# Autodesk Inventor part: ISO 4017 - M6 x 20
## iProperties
Created: 2006-11
Part Number: ISO 4017 - M6 x 20
Material: Stahl, weich, unlegiert
Description: Sechskantschraube
Vendor: Autodesk Inc.
Document SubType Name: Modeling
Standard: ISO 4017
Designer: Schmidt
Standards Organization: DIN
Language: de-DE
Size Designation: M6 x 20
Categories: <MemberInstance Version="R10.0.0"><Categories><Category DisplayName="Schrauben" InternalName="e4da775c-781d-43d5-af7c-5136215cf5a6" Mnemonic="FSTN"><Category Di
Density: 7.86 g/cm^3
Author: Schmidt
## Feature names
1. Körper [Revolution]
2. Kopf [Extrusion]
3. Fase1 [Revolution]
4. Fase2 [Chamfer]
